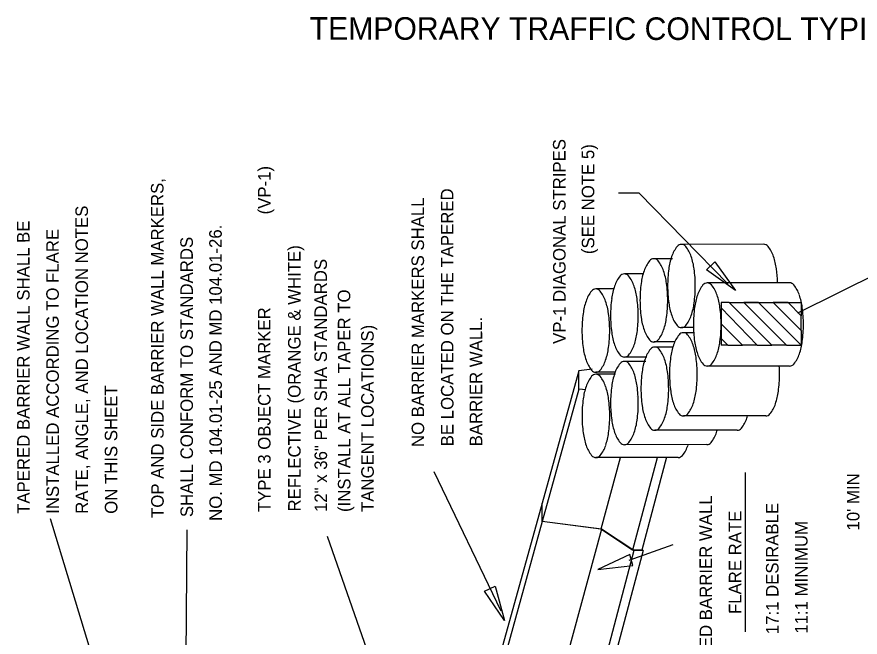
# Model space of a CAD drawing. Extents: x 612.5 to 619.9, y 611 to 621.1.
# Drawn here: x 612.612 to 616.652, y 618.122 to 621.092 of the extents above; entities that cross this region are included whole.
import ezdxf

# ---------------------------------------------------------------- set-up
doc = ezdxf.new("R2010")
doc.units = 0
for name, color, linetype in [('DETL-DIMS', 7, 'Continuous'), ('DETL-LINE', 7, 'Continuous'), ('DETL-NOTE', 7, 'Continuous'), ('DETL-TITL', 7, 'Continuous')]:
    doc.layers.add(name, color=color, linetype=linetype)

msp = doc.modelspace()

# ---------------------------------------------------------------- linework, layer by layer
at = {"layer": 'DETL-DIMS'}
for p, q in [((615.5928, 620.2478), (615.4953, 620.2478)), ((616.019, 619.8131), (615.5928, 620.2478)), ((616.3538, 619.6746), (616.8298, 619.9116)), ((614.932, 618.247), (614.6116, 618.914)), ((616.1016, 618.9107), (616.1021, 618.1469)), ((612.7711, 618.6898), (613.2439, 617.1366)), ((613.4174, 616.9852), (613.4272, 618.6358)), ((614.423, 617.6829), (614.0995, 618.6033)), ((615.546, 618.4908), (615.7562, 618.5653))]:
    msp.add_line(p, q, dxfattribs=at)
for points in [[(615.9164, 619.8803), (615.9557, 619.9199), (616.055, 619.7819)], [(615.564, 618.4648), (615.5491, 618.5186), (615.3951, 618.4468)], [(614.8532, 618.343), (614.9039, 618.3663), (614.9484, 618.2024)]]:
    msp.add_lwpolyline(points, close=True, dxfattribs=at)
at = {"layer": 'DETL-LINE'}
for p, q in [((616.1905, 620.003), (615.7961, 620.0028)), ((615.753, 619.934), (615.6638, 619.9339)), ((615.6162, 619.8616), (615.5226, 619.8616)), ((616.3142, 619.8187), (615.9198, 619.8185)), ((615.475, 619.7892), (615.3858, 619.7892)), ((615.9863, 619.7242), (615.9863, 619.5201)), ((615.9863, 619.7242), (615.9863, 619.6988)), ((616.025, 619.7242), (615.9863, 619.7242)), ((615.9863, 619.7242), (615.9863, 619.6988)), ((615.9863, 619.7242), (615.9863, 619.6988)), ((616.025, 619.7242), (616.0955, 619.7242)), ((616.2291, 619.5201), (616.025, 619.7242)), ((616.0955, 619.7242), (616.166, 619.7242)), ((616.0955, 619.7242), (616.2996, 619.5201)), ((616.166, 619.7242), (616.2364, 619.7242)), ((616.166, 619.7242), (616.37, 619.5201)), ((616.2364, 619.7242), (616.3068, 619.7242)), ((616.2364, 619.7242), (616.37, 619.5906)), ((616.3068, 619.7242), (616.37, 619.7242)), ((616.3068, 619.7242), (616.37, 619.661)), ((616.37, 619.7242), (616.37, 619.661)), ((615.9863, 619.6988), (616.1587, 619.5201)), ((616.37, 619.5906), (616.37, 619.661)), ((615.8547, 619.6041), (615.7963, 619.6041)), ((615.9863, 619.622), (616.0882, 619.5201)), ((615.8591, 619.5799), (615.8052, 619.5799)), ((616.37, 619.5906), (616.37, 619.5201)), ((615.7637, 619.5354), (615.664, 619.5354)), ((615.9863, 619.5515), (616.0178, 619.5201)), ((616.0178, 619.5201), (615.9863, 619.5201)), ((616.0178, 619.5201), (616.0882, 619.5201)), ((616.1587, 619.5201), (616.0882, 619.5201)), ((616.1587, 619.5201), (616.2291, 619.5201)), ((616.2996, 619.5201), (616.2291, 619.5201)), ((616.2996, 619.5201), (616.37, 619.5201)), ((615.755, 619.5112), (615.6685, 619.5111)), ((615.6298, 619.463), (615.5228, 619.463)), ((615.6253, 619.4424), (615.5228, 619.4424)), ((615.3051, 619.3978), (615.1291, 618.7643)), ((615.3052, 619.31), (615.3051, 619.3978)), ((615.3689, 619.4054), (615.3052, 619.3977)), ((616.3144, 619.4202), (615.9201, 619.4198)), ((615.4798, 619.3906), (615.3861, 619.3906)), ((615.4798, 619.3809), (615.3861, 619.3808)), ((615.3052, 619.3103), (615.1291, 618.6762)), ((615.3383, 619.3061), (615.3054, 619.3103)), ((615.5831, 619.2746), (615.5828, 619.2746)), ((616.1998, 619.1815), (615.8055, 619.1812)), ((616.0631, 619.1128), (615.6687, 619.1125)), ((615.9176, 619.044), (615.5231, 619.0437)), ((615.7808, 618.9825), (615.3864, 618.9822)), ((615.5027, 618.9801), (615.4101, 618.6399)), ((615.6795, 618.9801), (615.5623, 618.5392)), ((615.7246, 618.9836), (615.6064, 618.5391)), ((615.1291, 618.764), (614.7791, 617.5038)), ((615.1292, 618.6761), (615.1291, 618.7639)), ((615.1292, 618.6762), (615.1292, 618.764)), ((615.1291, 618.6762), (614.7792, 617.416)), ((615.4101, 618.6399), (615.1292, 618.6762)), ((615.413, 618.6394), (615.1292, 618.6761)), ((615.413, 618.6395), (615.0931, 617.4655)), ((615.5624, 618.5391), (615.4101, 618.6399)), ((615.5685, 618.5364), (615.413, 618.6394)), ((615.5684, 618.5365), (615.2836, 617.4655)), ((615.6126, 618.5365), (615.3278, 617.4656)), ((615.6067, 618.5391), (615.5624, 618.5391)), ((615.6128, 618.5365), (615.5685, 618.5364))]:
    msp.add_line(p, q, dxfattribs=at)
for points in [[(616.025, 619.7242), (615.9863, 619.7242), (615.9863, 619.6988), (616.1587, 619.5201), (616.2291, 619.5201)], [(616.0955, 619.7242), (616.2996, 619.5201), (616.37, 619.5201), (616.166, 619.7242)], [(616.2364, 619.7242), (616.37, 619.5906), (616.37, 619.661), (616.3068, 619.7242)], [(615.9863, 619.622), (615.9863, 619.5515), (616.0178, 619.5201), (616.0882, 619.5201)]]:
    msp.add_lwpolyline(points, close=True, dxfattribs=at)
msp.add_lwpolyline([(615.9863, 619.5515), (616.0178, 619.5201), (616.0882, 619.5201), (615.9863, 619.622)], dxfattribs=at)
for centre, radius, start, end in [((615.7961, 619.9765), 0.0263, 90.0399, 141.2149), ((615.7961, 619.9765), 0.0263, 38.8648, 90.0399), ((616.1905, 619.9767), 0.0263, 38.8648, 90.0399), ((615.8975, 619.895), 0.1563, 141.2149, 161.6049), ((615.6948, 619.8948), 0.1563, 18.4748, 38.8648), ((616.0892, 619.8951), 0.1563, 18.4748, 38.8648), ((615.7652, 619.8262), 0.1563, 141.2149, 161.6049), ((615.6638, 619.9077), 0.0263, 90.0399, 141.2149), ((615.6638, 619.9077), 0.0263, 38.8648, 90.0399), ((615.5625, 619.8261), 0.1563, 18.4748, 38.8648), ((616.0626, 619.8401), 0.3304, 161.6049, 172.1787), ((615.5298, 619.8397), 0.3304, 7.9011, 18.4748), ((615.9242, 619.84), 0.3304, 7.9011, 18.4748), ((616.3267, 619.8038), 0.5969, 172.1787, 180.0399), ((615.2657, 619.8031), 0.5969, 0.0399, 7.9011), ((615.6601, 619.8033), 0.5969, 1.7555, 7.9011), ((615.624, 619.7538), 0.1563, 141.2149, 161.6049), ((615.5226, 619.8353), 0.0263, 90.0399, 141.2149), ((615.5226, 619.8353), 0.0263, 38.8648, 90.0399), ((615.4213, 619.7537), 0.1563, 18.4748, 38.8648), ((615.9303, 619.7713), 0.3304, 161.6049, 172.1787), ((615.3974, 619.7709), 0.3304, 7.9011, 18.4748), ((615.7891, 619.6989), 0.3304, 161.6049, 172.1787), ((615.2562, 619.6986), 0.3304, 7.9011, 18.4748), ((616.1944, 619.735), 0.5969, 172.1787, 180.0399), ((615.1334, 619.7343), 0.5969, 0.0399, 7.9011), ((616.3267, 619.8038), 0.5969, 180.0399, 187.9011), ((615.2657, 619.8031), 0.5969, 352.1787, 0.0399), ((616.0212, 619.7107), 0.1563, 141.2149, 161.6049), ((615.9198, 619.7922), 0.0263, 90.0399, 141.2149), ((615.9198, 619.7922), 0.0263, 38.8648, 90.0399), ((615.8185, 619.7106), 0.1563, 18.4748, 38.8648), ((616.3142, 619.7925), 0.0263, 38.8648, 90.0399), ((616.2129, 619.7109), 0.1563, 18.4748, 38.8648), ((615.4872, 619.6815), 0.1563, 141.2149, 161.6049), ((615.3858, 619.7629), 0.0263, 90.0399, 141.2149), ((615.3858, 619.7629), 0.0263, 38.8648, 90.0399), ((615.2845, 619.6813), 0.1563, 18.4748, 38.8648), ((616.1863, 619.6558), 0.3304, 161.6049, 172.1787), ((615.6535, 619.6555), 0.3304, 7.9011, 18.4748), ((616.0479, 619.6557), 0.3304, 7.9011, 18.4748), ((615.6524, 619.6265), 0.3304, 161.6049, 172.1787), ((615.1195, 619.6262), 0.3304, 7.9011, 18.4748), ((616.0532, 619.6626), 0.5969, 172.1787, 180.0399), ((614.9922, 619.6619), 0.5969, 0.0399, 7.9011), ((616.1944, 619.735), 0.5969, 180.0399, 187.9011), ((615.1334, 619.7343), 0.5969, 352.1787, 0.0399), ((616.0627, 619.7672), 0.3304, 187.9011, 198.4748), ((615.5298, 619.7668), 0.3304, 341.6049, 352.1787), ((616.4504, 619.6196), 0.5969, 172.1787, 180.0399), ((615.3894, 619.6188), 0.5969, 0.0399, 7.9011), ((615.7838, 619.6191), 0.5969, 0.0399, 7.9011), ((615.9164, 619.5903), 0.5969, 172.1787, 180.0399), ((614.8555, 619.5895), 0.5969, 0.0399, 7.9011), ((616.0532, 619.6626), 0.5969, 180.0399, 187.9011), ((614.9922, 619.6619), 0.5969, 352.1787, 0.0399), ((615.9303, 619.6984), 0.3304, 187.9011, 198.4748), ((615.3975, 619.698), 0.3304, 341.6049, 352.1787), ((615.8976, 619.712), 0.1563, 198.4748, 218.8648), ((615.6949, 619.7119), 0.1563, 321.2149, 341.6049), ((615.7963, 619.6304), 0.0263, 218.8648, 270.0399), ((615.7963, 619.6304), 0.0263, 270.0399, 321.2149), ((616.4504, 619.6196), 0.5969, 180.0399, 187.9011), ((615.3894, 619.6188), 0.5969, 352.1787, 0.0399), ((615.7838, 619.6191), 0.5969, 352.1787, 0.0399), ((615.9164, 619.5903), 0.5969, 180.0399, 187.9011), ((614.8555, 619.5895), 0.5969, 352.1787, 0.0399), ((615.7892, 619.626), 0.3304, 187.9011, 198.4748), ((615.2563, 619.6256), 0.3304, 341.6049, 352.1787), ((615.7653, 619.6432), 0.1563, 198.4748, 218.8648), ((615.5626, 619.6431), 0.1563, 321.2149, 341.6049), ((615.9066, 619.4721), 0.1563, 141.2149, 161.6049), ((615.8052, 619.5536), 0.0263, 90.0399, 141.2149), ((615.8052, 619.5536), 0.0263, 38.8648, 90.0399), ((615.7039, 619.472), 0.1563, 18.4748, 38.8648), ((615.6241, 619.5709), 0.1563, 198.4748, 218.8648), ((615.4214, 619.5707), 0.1563, 321.2149, 341.6049), ((615.664, 619.5616), 0.0263, 218.8648, 270.0399), ((615.664, 619.5616), 0.0263, 270.0399, 321.2149), ((616.0717, 619.4172), 0.3304, 161.6049, 172.1787), ((615.5389, 619.4168), 0.3304, 7.9011, 18.4748), ((616.1864, 619.5829), 0.3304, 187.9011, 198.4748), ((615.6535, 619.5825), 0.3304, 341.6049, 352.1787), ((616.0479, 619.5828), 0.3304, 341.6049, 352.1787), ((615.6524, 619.5536), 0.3304, 187.9011, 198.4748), ((615.1195, 619.5533), 0.3304, 341.6049, 352.1787), ((615.7699, 619.4034), 0.1563, 141.2149, 161.6049), ((615.6685, 619.4848), 0.0263, 90.0399, 141.2149), ((615.6685, 619.4848), 0.0263, 38.8648, 90.0399), ((615.5672, 619.4032), 0.1563, 18.4748, 38.8648), ((616.0213, 619.5278), 0.1563, 198.4748, 218.8648), ((615.8186, 619.5276), 0.1563, 321.2149, 341.6049), ((616.213, 619.5279), 0.1563, 321.2149, 341.6049), ((615.4874, 619.4985), 0.1563, 198.4748, 218.8648), ((615.2847, 619.4983), 0.1563, 321.2149, 341.6049), ((615.5228, 619.4892), 0.0263, 218.8648, 270.0399), ((615.5229, 619.4161), 0.0263, 90.0399, 141.2149), ((615.5228, 619.4892), 0.0263, 270.0399, 321.2149), ((615.5229, 619.4161), 0.0263, 38.8648, 90.0399), ((615.935, 619.3484), 0.3304, 161.6049, 172.1787), ((615.4021, 619.3481), 0.3304, 7.9011, 18.4748), ((616.3358, 619.3809), 0.5969, 172.1787, 180.0399), ((615.2749, 619.3802), 0.5969, 0.0399, 7.9011), ((615.3861, 619.4169), 0.0263, 218.8648, 270.0399), ((615.3861, 619.4169), 0.0263, 270.0399, 321.2149), ((615.6243, 619.3346), 0.1563, 141.2149, 161.6049), ((615.4216, 619.3345), 0.1563, 18.4748, 38.8648), ((615.92, 619.4461), 0.0263, 218.8648, 270.0399), ((615.92, 619.4461), 0.0263, 270.0399, 321.2149), ((615.6693, 619.3805), 0.5969, 0.0399, 3.8478), ((616.3144, 619.4464), 0.0263, 270.0399, 321.2149), ((615.4875, 619.2731), 0.1563, 141.2149, 161.6049), ((615.3861, 619.3545), 0.0263, 90.0399, 141.2149), ((615.3861, 619.3545), 0.0263, 38.8648, 90.0399), ((615.2848, 619.2729), 0.1563, 18.4748, 38.8648), ((615.7894, 619.2797), 0.3304, 161.6049, 172.1787), ((615.2565, 619.2793), 0.3304, 7.9011, 18.4748), ((616.1991, 619.3122), 0.5969, 172.1787, 180.0399), ((615.1381, 619.3114), 0.5969, 0.0399, 7.9011), ((616.3358, 619.3809), 0.5969, 180.0399, 187.9011), ((615.2749, 619.3802), 0.5969, 352.1787, 0.0399), ((615.6693, 619.3805), 0.5969, 352.1787, 0.0399), ((615.6526, 619.2181), 0.3304, 161.6049, 172.1787), ((615.1198, 619.2178), 0.3304, 7.9011, 18.4748), ((616.0535, 619.2434), 0.5969, 172.1787, 180.0399), ((614.9925, 619.2427), 0.5969, 0.0399, 7.9011), ((616.1991, 619.3122), 0.5969, 180.0399, 187.9011), ((615.1381, 619.3114), 0.5969, 352.1787, 0.0399), ((616.0718, 619.3443), 0.3304, 187.9011, 198.4748), ((615.5389, 619.3439), 0.3304, 341.6049, 352.1787), ((615.9333, 619.3442), 0.3304, 341.6049, 352.1787), ((615.9167, 619.1819), 0.5969, 172.1787, 180.0399), ((614.8557, 619.1811), 0.5969, 0.0399, 7.9011), ((616.0535, 619.2434), 0.5969, 180.0399, 187.9011), ((614.9925, 619.2427), 0.5969, 352.1787, 0.0399), ((615.9067, 619.2892), 0.1563, 198.4748, 218.8648), ((615.7041, 619.289), 0.1563, 321.2149, 341.6049), ((616.0985, 619.2893), 0.1563, 321.2149, 341.6049), ((615.935, 619.2755), 0.3304, 187.9011, 198.4748), ((615.4022, 619.2752), 0.3304, 341.6049, 352.1787), ((615.9167, 619.1819), 0.5969, 180.0399, 187.9011), ((614.8557, 619.1811), 0.5969, 352.1787, 0.0399), ((615.7895, 619.2068), 0.3304, 187.9011, 198.4748), ((615.2566, 619.2064), 0.3304, 341.6049, 352.1787), ((615.77, 619.2204), 0.1563, 198.4748, 218.8648), ((615.5673, 619.2202), 0.1563, 321.2149, 341.6049), ((615.8055, 619.2075), 0.0263, 218.8648, 270.0399), ((615.8055, 619.2075), 0.0263, 270.0399, 321.2149), ((615.9617, 619.2205), 0.1563, 321.2149, 341.6049), ((615.7966, 619.2754), 0.3304, 341.6049, 343.4325), ((616.1999, 619.2078), 0.0263, 270.0399, 321.2149), ((615.6687, 619.1388), 0.0263, 218.8648, 270.0399), ((615.6687, 619.1388), 0.0263, 270.0399, 321.2149), ((615.651, 619.2067), 0.3304, 341.6049, 343.65), ((616.0631, 619.139), 0.0263, 270.0399, 321.2149), ((615.6527, 619.1452), 0.3304, 187.9011, 198.4748), ((615.1198, 619.1449), 0.3304, 341.6049, 352.1787), ((615.6244, 619.1516), 0.1563, 198.4748, 218.8648), ((615.4217, 619.1515), 0.1563, 321.2149, 341.6049), ((615.8161, 619.1518), 0.1563, 321.2149, 341.6049), ((615.4876, 619.0901), 0.1563, 198.4748, 218.8648), ((615.285, 619.0899), 0.1563, 321.2149, 341.6049), ((615.5231, 619.07), 0.0263, 218.8648, 270.0399), ((615.5231, 619.07), 0.0263, 270.0399, 321.2149), ((615.6794, 619.0902), 0.1563, 321.2149, 341.6049), ((615.5142, 619.1451), 0.3304, 341.6049, 341.6349), ((615.9175, 619.0703), 0.0263, 270.0399, 321.2149), ((615.3864, 619.0085), 0.0263, 218.8648, 270.0399), ((615.3864, 619.0085), 0.0263, 270.0399, 321.2149), ((615.7808, 619.0087), 0.0263, 270.0399, 321.2149)]:
    msp.add_arc(centre, radius, start, end, dxfattribs=at)

# ---------------------------------------------------------------- texts
at = {"layer": 'DETL-NOTE'}
for s, p in [('VP-1 DIAGONAL STRIPES', (615.2413, 619.5263)), ('(SEE NOTE 5)', (615.3787, 619.9563)), ('(VP-1)', (613.8274, 620.1463)), ('TOP AND SIDE BARRIER WALL MARKERS,', (613.3155, 618.693)), ('BE LOCATED ON THE TAPERED', (614.7041, 619.036)), ('NO BARRIER MARKERS SHALL', (614.5634, 619.0324)), ('RATE, ANGLE, AND LOCATION NOTES', (612.9535, 618.7127)), ('TAPERED BARRIER WALL SHALL BE', (612.6735, 618.7125)), ('NO. MD 104.01-25 AND MD 104.01-26.', (613.5945, 618.6789)), ('INSTALLED ACCORDING TO FLARE ', (612.8135, 618.7126)), ('SHALL CONFORM TO STANDARDS', (613.456, 618.697)), ('REFLECTIVE (ORANGE & WHITE)', (613.9718, 618.7239)), ('12" x 36" PER SHA STANDARDS', (614.0983, 618.7214)), ('(INSTALL AT ALL TAPER TO ', (614.2103, 618.7214)), ('TYPE 3 OBJECT MARKER', (613.8275, 618.7208)), ('BARRIER WALL.', (614.8417, 619.0358)), ('TANGENT LOCATIONS)', (614.3222, 618.7215)), ('ON THIS SHEET ', (613.0935, 618.7128)), ("10' MIN", (616.6489, 618.633)), ('TAPERED BARRIER WALL', (615.9431, 617.802)), (' 17:1 DESIRABLE', (616.2614, 618.114)), ('FLARE RATE', (616.0832, 618.2329)), (' 11:1 MINIMUM', (616.4006, 618.1165))]:
    msp.add_text(s, height=0.06, rotation=90.0399, dxfattribs=at).set_placement(p)
at = {"layer": 'DETL-TITL'}
msp.add_text('TEMPORARY TRAFFIC CONTROL TYPICAL APPLICATION', height=0.108, rotation=359.9601, dxfattribs=at).set_placement((614.0149, 620.9828))

doc.saveas('drawing.dxf')
